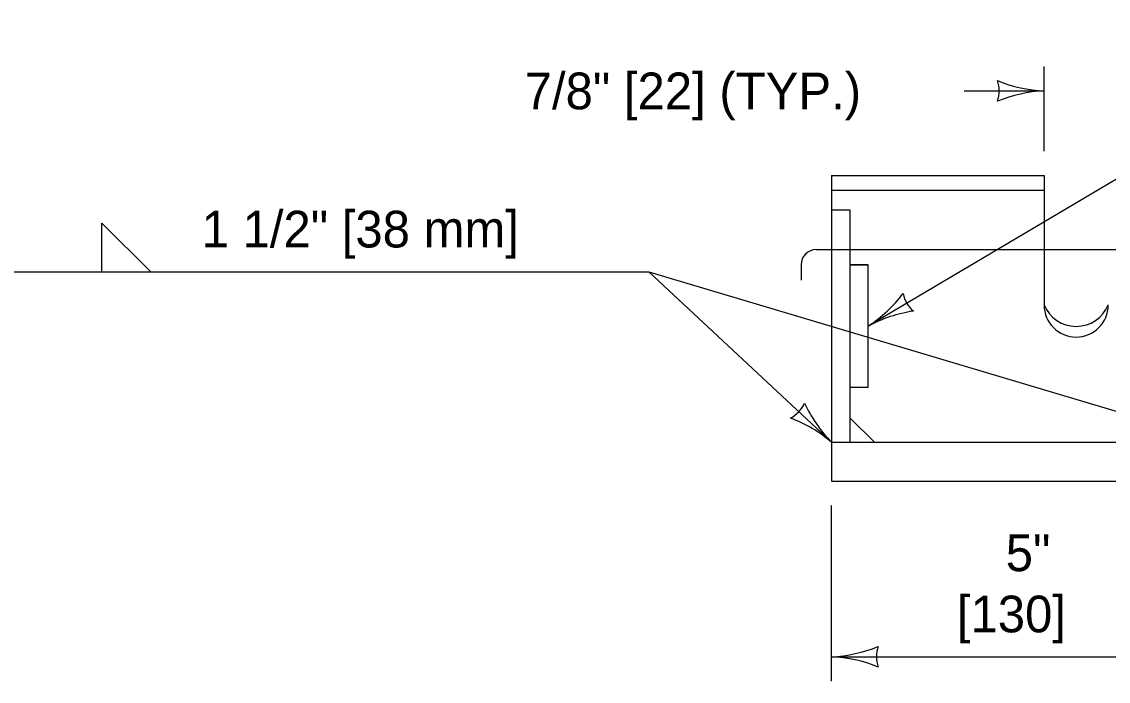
# Model space of a CAD drawing. Extents: x 49991.4 to 50021, y 49987.6 to 50011.4.
# Drawn here: x 50011.457 to 50013.234, y 49992.915 to 49993.994 of the extents above; entities that cross this region are included whole.
import ezdxf

# ---------------------------------------------------------------- set-up
doc = ezdxf.new("R2010")
doc.units = 0
for name, color, linetype in [('Level 1', 7, 'Continuous'), ('Level 2', 7, 'Continuous'), ('Level 3', 7, 'Continuous'), ('Level 4', 7, 'Continuous')]:
    doc.layers.add(name, color=color, linetype=linetype)

msp = doc.modelspace()

# ---------------------------------------------------------------- linework, layer by layer
at = {"layer": 'Level 1'}
for p, q in [((50012.7813, 49993.7421), (50012.7813, 49993.2426)), ((50012.7813, 49993.7421), (50013.1288, 49993.7421)), ((50013.1288, 49993.7421), (50013.1288, 49993.5306)), ((50012.7813, 49993.7181), (50013.1288, 49993.7181)), ((50012.7813, 49993.6861), (50012.8113, 49993.6861)), ((50012.8113, 49993.6861), (50012.8113, 49993.3061)), ((50012.7563, 49993.6211), (50012.7813, 49993.6211)), ((50012.8113, 49993.6211), (50013.4163, 49993.6211)), ((50012.7313, 49993.5961), (50012.7313, 49993.5711)), ((50012.8113, 49993.5961), (50012.8413, 49993.5961)), ((50012.8413, 49993.3961), (50012.8413, 49993.5961)), ((50012.8113, 49993.3961), (50012.8413, 49993.3961)), ((50012.8513, 49993.3061), (50012.8113, 49993.3461)), ((50012.7813, 49993.3061), (50014.5313, 49993.3061)), ((50012.7813, 49993.2426), (50014.5313, 49993.2426))]:
    msp.add_line(p, q, dxfattribs=at)
for points in [[(50012.8113, 49993.5961), (50012.8113, 49993.3961), (50012.8413, 49993.3961), (50012.8413, 49993.5961), (50012.8113, 49993.5961)], [(50012.8113, 49993.3061), (50012.8513, 49993.3061), (50012.8113, 49993.3461), (50012.8113, 49993.3061)]]:
    msp.add_lwpolyline(points, dxfattribs=at)
for centre, radius, start, end in [((50012.7563, 49993.5961), 0.025, 90, 180), ((50013.1813, 49993.5306), 0.0525, 180, 270), ((50013.1813, 49993.5525), 0.0569, 202.6199, 337.3801), ((50013.1813, 49993.5306), 0.0525, 270, 0)]:
    msp.add_arc(centre, radius, start, end, dxfattribs=at)
at = {"layer": 'Level 3'}
for p, q in [((50013.6813, 49993.9937), (50012.8413, 49993.4961)), ((50013.1288, 49993.7821), (50013.1288, 49993.9206)), ((50012.9983, 49993.8806), (50013.1288, 49993.8806)), ((50011.5877, 49993.6646), (50011.6677, 49993.5846)), ((50011.5877, 49993.5846), (50011.5877, 49993.6646)), ((50010.9338, 49993.5846), (50012.4821, 49993.5846)), ((50012.4821, 49993.5846), (50012.7813, 49993.3061)), ((50012.4821, 49993.5846), (50013.4163, 49993.3061)), ((50012.7813, 49992.9153), (50012.7813, 49993.2026)), ((50012.7813, 49992.9553), (50013.4313, 49992.9553))]:
    msp.add_line(p, q, dxfattribs=at)
for centre, radius, start, end in [((50013.138, 49994.1027), 0.2223, 247.456, 267.6395), ((50013.0006, 49993.8806), 0.0548, 342.1388, 17.8612), ((50013.1403, 49993.6479), 0.233, 92.8273, 112.0772), ((50012.7128, 49993.6904), 0.233, 303.4697, 322.7196), ((50012.9516, 49993.5614), 0.0548, 192.7813, 228.5036), ((50012.9466, 49993.3003), 0.2223, 98.0984, 118.282), ((50012.6875, 49993.3934), 0.0548, 299.1911, 334.9135), ((50012.9394, 49993.4624), 0.2223, 204.5083, 224.6918), ((50012.6312, 49993.1279), 0.233, 49.8796, 69.1295), ((50012.7698, 49993.188), 0.233, 272.8273, 292.0772), ((50012.9095, 49992.9553), 0.0548, 162.1388, 197.8612), ((50012.7721, 49992.7332), 0.2223, 67.456, 87.6395)]:
    msp.add_arc(centre, radius, start, end, dxfattribs=at)
at = {"layer": 'Level 4'}
msp.add_line((50012.7813, 49993.6211), (50012.8113, 49993.6211), dxfattribs=at)

# ---------------------------------------------------------------- texts
at = {"layer": 'Level 2'}
for s, p in [('7/8" [22] (TYP.)', (50012.2793, 49993.8506)), ('1 1/2" [38 mm]', (50011.7509, 49993.6246)), ('5"', (50013.0661, 49993.0953)), ('[130]', (50012.9862, 49992.9953))]:
    msp.add_text(s, height=0.06, dxfattribs=at).set_placement(p)

doc.saveas('drawing.dxf')
